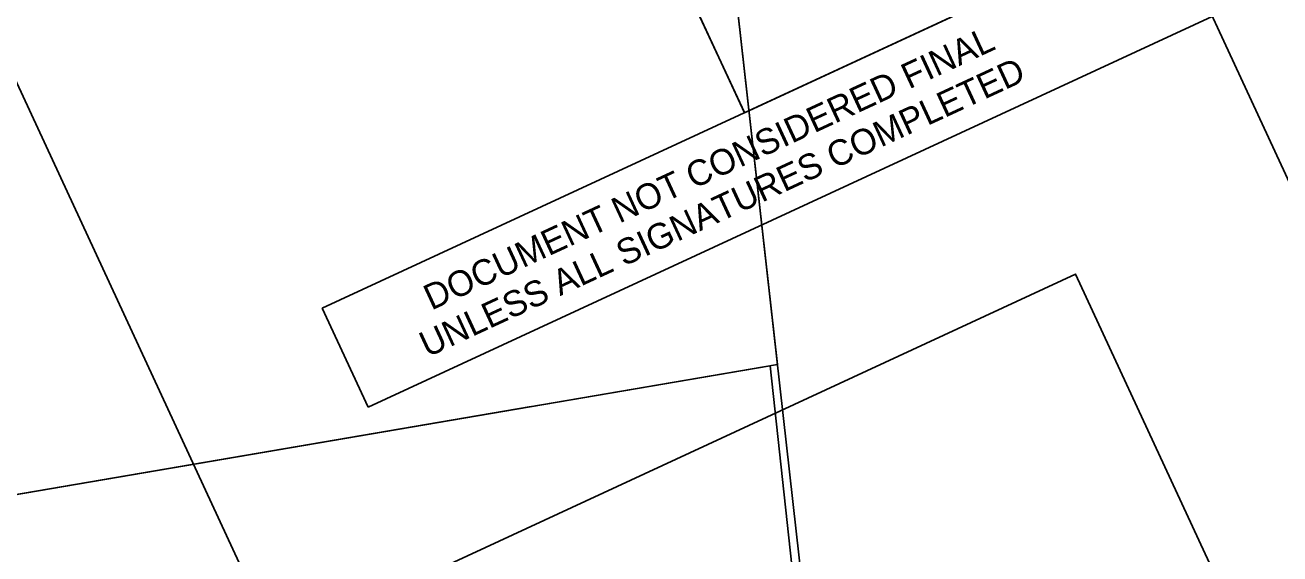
# Model space of a CAD drawing. Extents: x 1722892 to 1724880, y 971019 to 972720.
# Drawn here: x 1724231.4 to 1724501.2, y 972419.6 to 972533.3 of the extents above; entities that cross this region are included whole.
import ezdxf

# ---------------------------------------------------------------- set-up
doc = ezdxf.new("R2010")
doc.units = 0
for name, color, linetype in [('Matchline', 7, 'Continuous'), ('Sheet Clip Boundary CELL', 7, 'Continuous'), ('Sheet Layout Plan Border', 7, 'Continuous'), ('Sheet Plan CELL', 7, 'Continuous'), ('Sheet Sticker Exception Certification CELL', 7, 'Continuous')]:
    doc.layers.add(name, color=color, linetype=linetype)

msp = doc.modelspace()

# ---------------------------------------------------------------- linework, layer by layer
at = {"layer": 'Matchline'}
msp.add_line((1724068.11, 972404.72), (1724340.27, 972451.29), dxfattribs=at)
at = {"layer": 'Sheet Clip Boundary CELL'}
msp.add_lwpolyline([(1723539.64, 971130.3), (1724809.87, 971718.99), (1724457.28, 972479.77), (1724285.57, 972400.19), (1724196.64, 972592.07), (1723098.13, 972082.96)], close=True, dxfattribs=at)
at = {"layer": 'Sheet Layout Plan Border'}
for points in [[(1724374.31, 972628.66), (1724393.21, 972460.35), (1724068.11, 972404.72), (1724049.69, 972271.07), (1723832.27, 972270.2), (1723815.72, 972244.69), (1723599.72, 972315.43), (1723098.13, 972082.96), (1723600.74, 971158.62), (1723483.33, 971374.55), (1723802.12, 971464.67), (1724031.92, 971474.7), (1724072.16, 971562.21), (1724326.28, 971494.87), (1724493, 971572.14)], [(1724391.63, 972460.07), (1724068.11, 972404.72), (1724049.69, 972271.07), (1723832.27, 972270.2), (1723815.72, 972244.69), (1723599.72, 972315.43), (1723098.13, 972082.96), (1723600.74, 971158.62), (1723483.33, 971374.55), (1723802.12, 971464.67), (1724031.92, 971474.7), (1724072.16, 971562.21), (1724326.28, 971494.87), (1724488.18, 971569.9)]]:
    msp.add_lwpolyline(points, close=True, dxfattribs=at)
at = {"layer": 'Sheet Plan CELL'}
msp.add_line((1724338.78, 972616.55), (1724386.09, 972514.52), dxfattribs=at)
for points in [[(1724413.74, 972692.69), (1723052.76, 972061.94), (1723494.28, 971109.28), (1724855.24, 971740.02)], [(1724338.78, 972616.55), (1724429.5, 972658.61), (1724476.82, 972556.53), (1724386.1, 972514.47)]]:
    msp.add_lwpolyline(points, close=True, dxfattribs=at)
at = {"layer": 'Sheet Sticker Exception Certification CELL'}
for p, q in [((1724295.32, 972472.43), (1724476.81, 972556.54)), ((1724486.7, 972535.22), (1724305.2, 972451.11)), ((1724305.2, 972451.11), (1724295.32, 972472.43))]:
    msp.add_line(p, q, dxfattribs=at)

# ---------------------------------------------------------------- texts
for s, p in [('DOCUMENT NOT CONSIDERED FINAL', (1724318.79, 972471.9)), ('UNLESS ALL SIGNATURES COMPLETED', (1724317.89, 972461.78))]:
    msp.add_text(s, height=5.5, rotation=24.8656, dxfattribs=at).set_placement(p)

doc.saveas('drawing.dxf')
